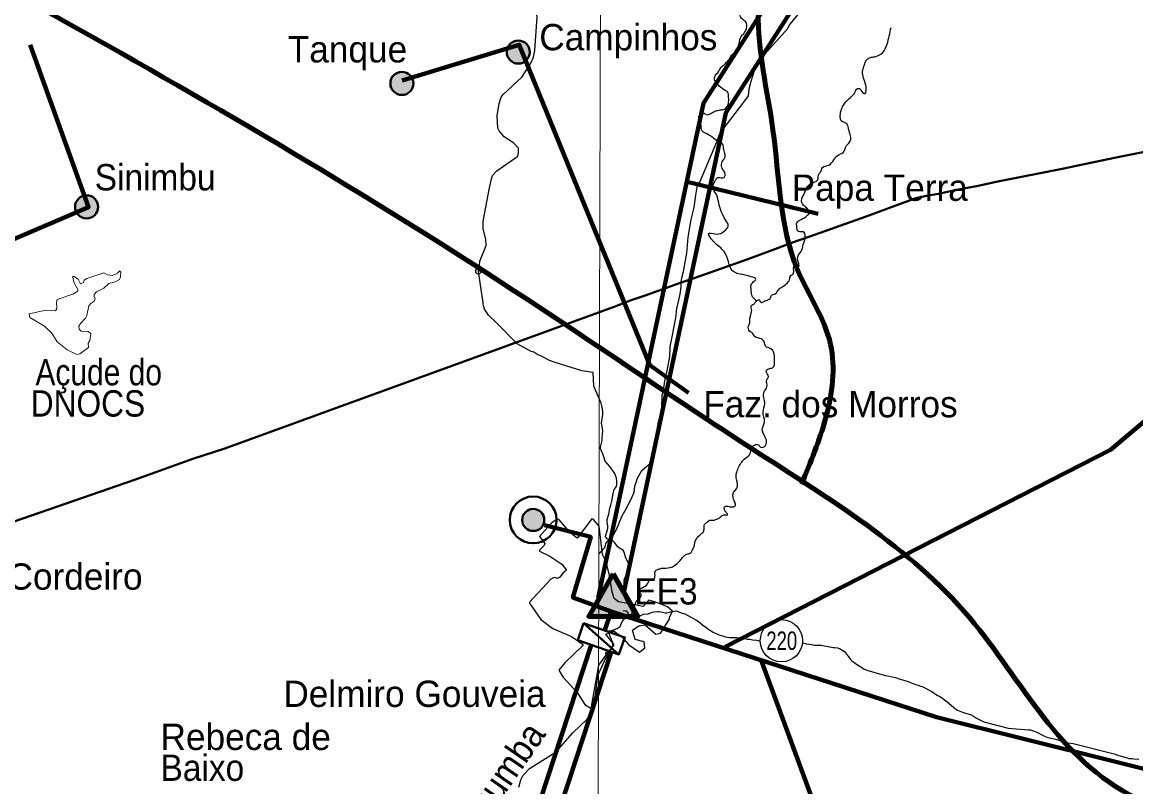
# Model space of a CAD drawing. Extents: x 553962 to 842807, y 8883888 to 9032388.
# Drawn here: x 598851 to 619995, y 8958889 to 8973416 of the extents above; entities that cross this region are included whole.
import ezdxf
from ezdxf.enums import TextEntityAlignment as Align

# ---------------------------------------------------------------- set-up
doc = ezdxf.new("R2010")
doc.units = 0
doc.header["$LTSCALE"] = 200
doc.header["$PDMODE"] = 32
doc.header["$PDSIZE"] = 100
for name, color, linetype, lineweight in [('1', 7, 'Continuous', 13), ('12', 7, 'Continuous', 25), ('21', 7, 'Continuous', 25), ('22', 7, 'Continuous', 13), ('24', 7, 'Continuous', 25), ('28', 7, 'Continuous', 40), ('41', 7, 'Continuous', 40), ('48', 7, 'Continuous', 25), ('9', 7, 'Continuous', 90)]:
    doc.layers.add(name, color=color, linetype=linetype, lineweight=lineweight)
doc.layers.add('49', color=7, linetype='Continuous')
doc.layers.add('50', color=7, linetype='Continuous')

msp = doc.modelspace()

# ---------------------------------------------------------------- hatches: boundary and pattern name
at = {"layer": '28'}
for points in [[(608763.6, 8963959.3, 1), (608342.8, 8963959.3, 1)], [(610074, 8962934.3), (610540.1, 8962126.9), (609607.9, 8962126.9)]]:
    msp.add_hatch(color=256, dxfattribs=at).paths.add_polyline_path(points)
at = {"layer": '41'}
for points in [[(608487.7, 8972849.2, 1), (608050.1, 8972849.2, 1)], [(606278, 8972253.9, 1), (605840.4, 8972253.9, 1)], [(600290.8, 8969907.7, 1), (599853.1, 8969907.7, 1)]]:
    msp.add_hatch(color=256, dxfattribs=at).paths.add_polyline_path(points)

# ---------------------------------------------------------------- linework, layer by layer
at = {"layer": '1'}
msp.add_lwpolyline([(609971.9, 9023551.8), (609764.7, 8949706.7), (609734.2, 8939404.4)], dxfattribs=at)
at = {"layer": '12'}
for points in [[(612832.5, 8972676.8), (613380.5, 8973289.6), (613425.9, 8973370.8), (613657.1, 8973648.4)], [(612040.3, 8971143.9), (612075.9, 8971248.3), (612161.5, 8971384.7), (612387.3, 8971680.5), (612554.1, 8971895.1), (612640.6, 8972015.5), (612654.9, 8972153.7), (612690.4, 8972298), (612756.6, 8972498.4), (612812.5, 8972654.7), (612832.5, 8972676.8)], [(611360.5, 8968467.9), (611360.9, 8968494.9), (611366.6, 8968506), (611377.4, 8968558.1), (611408, 8968681.3), (611469.3, 8969025.9), (611498.7, 8969332.5), (611555.6, 8969669.1), (611608.8, 8969893.5), (611644.5, 8970132.9), (611675.2, 8970318.3), (611717, 8970376.4), (612040.3, 8971143.9)], [(610973, 8965953.3), (610994.3, 8966098.6), (611002.5, 8966316), (611033.2, 8966472.2), (611059.2, 8966633.6), (611105, 8966822.9), (611145.7, 8967062.3), (611155.3, 8967247.7), (611194.3, 8967437), (611259.2, 8967798.7), (611279.7, 8967975), (611318.7, 8968135.3), (611346, 8968249.5), (611361.8, 8968386.8), (611360.5, 8968467.9)], [(609806.8, 8963316.2), (609840.1, 8963350.5), (609910.5, 8963433.7), (609927.6, 8963470.8), (609929.6, 8963512.9), (609970.7, 8963564), (610080.1, 8963678.4), (610134.1, 8963777.6), (610234.6, 8964027.2), (610293.4, 8964122.4), (610411.7, 8964351), (610469.1, 8964484.3), (610483.5, 8964599.5), (610535.5, 8964754.8), (610616.8, 8964899.1), (610667.4, 8964945.3), (610786.4, 8965043.6), (610825.3, 8965173.9), (610880.8, 8965525.5), (610933.4, 8965820.1), (610973, 8965953.3)], [(610264.1, 8962237.4), (610311.1, 8962234.5), (610316, 8962231.5), (610349.4, 8962192.5), (610374.6, 8962139.5), (610404.7, 8962083.4), (610408.2, 8962079.4), (610506.1, 8962105.6), (610649.1, 8962166.9), (610736.5, 8962174.1), (610812.1, 8962204.2), (610848.7, 8962215.3), (610911.8, 8962219.4), (610943.7, 8962217.5), (611006.1, 8962203.6), (611065.8, 8962194.6), (611093.8, 8962196.7), (611122.5, 8962202.7), (611157.7, 8962212.8), (611189.8, 8962219.9), (611269.6, 8962231), (611402.6, 8962182.1), (611435.5, 8962173.2), (611490.1, 8962144.2), (611638.5, 8962063.3), (611691.1, 8962029.4), (611771.1, 8961966.4), (611829.3, 8961918.4), (611889.1, 8961876.4), (611971.1, 8961828.5), (611997.8, 8961813.5), (612050.6, 8961788.6), (612077, 8961777.6), (612125.6, 8961761.6), (612153.7, 8961756.7), (612204.9, 8961738.7), (612281.6, 8961727.8), (612380.1, 8961723), (612410.5, 8961723), (612515.1, 8961715.2), (612566.3, 8961705.2), (612591.9, 8961698.3), (612616.6, 8961694.3), (612643, 8961692.3), (612669.5, 8961691.4), (612719.8, 8961683.5), (612795.6, 8961675.6), (612823.8, 8961668.6), (612864.6, 8961663.8)], [(613672.1, 8961625.4), (613738.4, 8961606.9), (613840.6, 8961591.1), (613866.3, 8961585.1), (613888.9, 8961581.1), (613942.1, 8961579.2), (613971.7, 8961581.3), (614023.1, 8961578.3), (614049.5, 8961572.4), (614124.5, 8961561.5), (614153.6, 8961554.5), (614252.3, 8961537.6), (614280.5, 8961536.7), (614332.5, 8961530.8), (614382, 8961510.8), (614463.3, 8961460.9), (614523.8, 8961379.8), (614532.2, 8961372.8), (614580.2, 8961308.8), (614605.9, 8961280.8), (614728.6, 8961192.9), (614806.5, 8961149.9), (614838.9, 8961123.9), (614908, 8961095), (615024.6, 8961065.1), (615056.6, 8961054.2), (615245.1, 8961000.4), (615313.2, 8960990.5), (615372, 8960976.5), (615403.6, 8960970.6), (615432.5, 8960962.6), (615523, 8960932.7), (615612.4, 8960910.8), (615673, 8960889.9), (615762.6, 8960853), (615820.4, 8960833), (615879.2, 8960814.1), (615910, 8960801.1), (615940.9, 8960791.2), (616125.3, 8960698.3), (616228.1, 8960625.3), (616267.4, 8960608.4), (616387.9, 8960522.4), (616444.1, 8960477.5), (616541.1, 8960393.5), (616575, 8960367.5), (616612, 8960346.5), (616675.8, 8960318.6), (616704.8, 8960308.6), (616763.6, 8960286.7), (616854.8, 8960258.8), (616911.9, 8960228.8), (616972.5, 8960193.8), (617033, 8960160.9), (617107.9, 8960123.1)], [(617107.9, 8960123.1), (617571.3, 8960000.1), (617961.2, 8959971.1), (617997, 8959967.1), (618026, 8959959.2), (618054, 8959949.2), (618114.7, 8959924.2), (618235.7, 8959862.3), (618293.7, 8959838.4), (618327.5, 8959827.4), (618413, 8959804.5), (618473.5, 8959791.6), (618533.2, 8959772.7), (618617.9, 8959748.8), (618652.5, 8959740.8), (618682.4, 8959731.8), (618711.4, 8959723.9), (618803.6, 8959709), (619586.3, 8959511.3)], [(619586.3, 8959511.3), (619636.3, 8959496), (619674.1, 8959485), (619831.3, 8959436.2)], [(619831.3, 8959436.2), (619865.1, 8959428.2), (619897.1, 8959423.3), (619929, 8959423.3), (619960.1, 8959421.4), (620056, 8959410.5)]]:
    msp.add_lwpolyline(points, dxfattribs=at)
at = {"layer": '12', "lineweight": 40}
for points in [[(621405.3, 8971207.1), (621164.3, 8971156.6), (620679.5, 8971055.7), (620194.7, 8970957.7), (619622.5, 8970843.7), (619047.4, 8970728.6), (618626.9, 8970634.8), (618210.5, 8970553), (617794.1, 8970471.2), (617379.1, 8970389.4), (616970.9, 8970302.6), (616723.1, 8970254.2)], [(616723.1, 8970254.2), (616475.2, 8970206.7), (616247.5, 8970158.2), (616024, 8970116.8), (615816.8, 8970075.4), (615681.8, 8970025.2), (615145.1, 8969827), (614804, 8969702.3), (614465.5, 8969579.5), (614127, 8969456.8), (613790, 8969340.1), (613461.1, 8969222.4), (613140.4, 8969103.7), (612819.7, 8968986), (612449.8, 8968852.2), (612021.1, 8968699.3), (611592.4, 8968549.4), (611360.5, 8968467.9)], [(611360.5, 8968467.9), (611013.3, 8968346.2), (610681, 8968223.4), (610434.1, 8968141.9), (610250.3, 8968070.5), (610141.5, 8968028.3), (609861, 8967928.7)], [(593118.3, 8961975.5), (594700.8, 8962547.5), (600985.5, 8964722.4), (602091.6, 8965119.9), (602697.1, 8965318.9), (609861, 8967928.7)]]:
    msp.add_lwpolyline(points, dxfattribs=at)
at = {"layer": '21'}
for points in [[(609804.3, 8963841.6), (609692.8, 8963976.2), (609666.6, 8963982.7), (609387.8, 8963613.5), (609268.7, 8963704.3), (609037.7, 8963969.7), (609005.2, 8963976.3), (608907.9, 8963902.9), (608765.2, 8963749.4), (608768.4, 8963752.9)], [(608768.4, 8963752.9), (608671.8, 8963644.5), (608771.6, 8963513.5), (608763, 8963472.8), (608674.7, 8963384.3), (608674.6, 8963362.6), (608871.1, 8963271.6), (609098.6, 8963116.9), (609185.2, 8963006.2), (609122.6, 8962955.4), (609059.5, 8962870.7), (609020.3, 8962848.1), (608953.3, 8962867.3), (608890.2, 8962830.9), (608482.3, 8962396.3), (608482.2, 8962374.6), (608698.7, 8962069.7), (608927.4, 8961894.7), (609281.9, 8961745.5), (609500, 8961592.1), (609485, 8961557.5), (609154.4, 8961246.1), (609040.8, 8961101.4), (609119, 8960979.5), (609387.8, 8960677.5), (609534.3, 8960449.1), (609653.8, 8960372.8), (609800.8, 8961196.1)], [(609800.8, 8961196.1), (609951.3, 8961405.5), (610091.2, 8961585.5), (609931.3, 8961785.4), (610001.3, 8961815.4), (610061.2, 8961845.4), (610091.2, 8961845.4), (610231.1, 8961745.4), (610371.1, 8961585.5), (610570.9, 8961445.5), (610670.8, 8961525.5), (610660.9, 8961645.5), (610491, 8961685.5), (610461, 8961775.4), (610441, 8961865.4), (610560.9, 8961945.4), (610680.8, 8961965.4), (610880.7, 8961785.4), (610970.7, 8961805.4), (611140.5, 8962075.3), (611140.5, 8962105.3), (611200.5, 8962225.3), (611100.6, 8962305.2), (610880.7, 8962395.2), (610750.8, 8962435.2), (610640.9, 8962315.2), (610391, 8962365.2), (610171.2, 8962405.2), (610091.2, 8962465.2), (610051.2, 8962595.2), (610001.3, 8962905.1), (609941.3, 8963165), (609871.4, 8963304.9), (609804.3, 8963841.6)]]:
    msp.add_lwpolyline(points, dxfattribs=at)
at = {"layer": '22'}
for points in [[(599809.1, 8968571.9), (599807.2, 8968579.6), (599825.8, 8968589.3), (599913, 8968531.8), (599957.7, 8968446.1), (600016.8, 8968470.3), (600024, 8968513.4), (600074.7, 8968549.4), (600397.5, 8968653.6), (600470.2, 8968613.3), (600565, 8968605), (600658.8, 8968647.2), (600702.7, 8968690.5), (600704.6, 8968688.3)], [(600704.6, 8968688.3), (600721.8, 8968668.3), (600716.4, 8968577.4), (600697.2, 8968526.2), (600615.2, 8968484), (600495.5, 8968451.8), (600399.8, 8968360.6), (600257.6, 8968290.3), (600215.3, 8968243.9), (600215.2, 8968203.3), (600238.2, 8968158.5), (600215, 8968118.4), (600157.8, 8968080.1), (600117.6, 8968027.2), (600078.7, 8967845.6), (600049.3, 8967791.2), (599953.8, 8967693.5), (599926.3, 8967638.5), (599930.5, 8967583.1), (599969.1, 8967544.5), (600104.8, 8967540.5), (600151.1, 8967502.5), (600134.3, 8967366.4), (600104.7, 8967317.5), (600109.2, 8967237.7)], [(598979.7, 8967874.9), (598979.6, 8967875.5), (599301.7, 8967946.2), (599480.2, 8967933.8), (599509.8, 8967969.9), (599501.3, 8968101.1), (599516.3, 8968150.1), (599811.5, 8968247.9), (599904.8, 8968303.2), (599909, 8968337.3), (599832.8, 8968479.3), (599809.1, 8968571.9)], [(599516.6, 8967344.8), (599411.9, 8967506.8), (599276.3, 8967640.2), (598993.8, 8967806), (598979.7, 8967874.9)], [(600109.2, 8967237.7), (599943.1, 8967117.9), (599886.4, 8967105.1), (599701.2, 8967194.2), (599516.6, 8967344.8)]]:
    msp.add_lwpolyline(points, dxfattribs=at)
at = {"layer": '24'}
msp.add_line((607511.6, 8968680.9), (607530.5, 8968802.4), dxfattribs=at)
for points in [[(607981.4, 8972045.9), (608340.3, 8972373.2), (608504, 8972626.3), (608557, 8972753.5), (608584.6, 8972880.9), (608629.2, 8973517.9), (608582.5, 8973773.1), (608506, 8973879.6), (608465.7, 8974028), (608448.7, 8974219.2), (608463.5, 8974525.1), (608412.1, 8974909.8)], [(608277, 8970937.8), (608271.1, 8971022.2), (608185.2, 8971119.9), (608000.5, 8971241), (607905, 8971351.2), (607881.9, 8971405.8), (607866.6, 8971636.1), (607904.8, 8971873.7), (607947.8, 8971995.4), (607981.4, 8972045.9)], [(607724.4, 8970268.8), (607758.4, 8970442.5), (607781.8, 8970504.1), (607860.2, 8970591), (608262.7, 8970873.9), (608277.1, 8970936.2), (608277, 8970937.8)], [(607530.5, 8968802.4), (607541.7, 8968874.6), (607660.5, 8969172.2), (607652.1, 8969290.7), (607601.1, 8969498.9), (607601.1, 8969639.1), (607724.4, 8970268.8)], [(607703.2, 8967850.5), (607627.7, 8967964.3), (607614.9, 8968008), (607605.5, 8968061.2), (607601.1, 8968086.8), (607511.6, 8968680.9)], [(608515.8, 8967162.6), (608251.1, 8967306.9), (607860.2, 8967694.8), (607703.2, 8967850.5)], [(609474.2, 8966790.4), (608973.4, 8966950.1), (608864.6, 8966990.5), (608731.8, 8967057), (608620.3, 8967109.1), (608563.4, 8967149.5), (608515.8, 8967162.6)], [(609841.5, 8966176.9), (609704.1, 8966503.7), (609693, 8966762.7), (609474.2, 8966790.4)], [(610371.4, 8962976.2), (610379.8, 8963013.8), (610382.1, 8963047.9), (610367.5, 8963120), (610314.8, 8963239.1), (610282.3, 8963338.2), (610265.4, 8963370.2), (610232.8, 8963402.2), (610193.3, 8963421.2), (610157.8, 8963448.2), (610095.6, 8963532.2), (610066.7, 8963561.2), (610036.6, 8963580.2), (610003.6, 8963581.1), (609956.2, 8963599.1), (609936, 8963623.1), (609928.6, 8963640.1), (609929.5, 8963669.1), (609954.4, 8963735.3), (609968.3, 8963800.4), (609967.7, 8963842.5), (609955.3, 8963923.6), (609957.6, 8963969.7), (609987.3, 8964065.8), (610009.7, 8964184.1), (610029.9, 8964242.2), (610049.4, 8964318.3), (610070.6, 8964459.6), (610090.6, 8964534.7), (610118.8, 8964569.8), (610136.5, 8964599.9), (610143.2, 8964627), (610143.3, 8964686.1), (610132.5, 8964751.1), (610117.5, 8964805.2), (610101.9, 8964839.2), (610009.9, 8964971.3), (609920.5, 8965076.3), (609887.1, 8965177.4), (609832.3, 8965315.6), (609830, 8965343.6), (609859.8, 8965469.8), (609861.1, 8965523.9), (609875.2, 8965654.1), (609872.3, 8965696.2), (609853, 8965796.3), (609874, 8965961.6), (609874.8, 8965999.7), (609869.2, 8966072.8), (609858.8, 8966126.9), (609841.5, 8966176.9)], [(609982.1, 8961422.7), (610037.1, 8961507.9), (610064.5, 8961578.1), (610064.2, 8961638.2), (610040.6, 8961677.2), (610038.1, 8961690.2), (610013.3, 8961743.3), (609992.6, 8961823.3), (609993.5, 8961853.4), (609997.6, 8961856.4), (610025.7, 8961851.5), (610048.1, 8961855.5), (610148.5, 8961896.7), (610207.6, 8961933.9), (610245.1, 8962026.1), (610277.6, 8962073.2), (610312.8, 8962103.3), (610398.6, 8962138.5), (610419.5, 8962164.6), (610435.7, 8962195.6), (610437.2, 8962206.7), (610284.5, 8962485.8), (610279.8, 8962547.9), (610295.5, 8962684.2), (610281.3, 8962752.3), (610279.8, 8962791.3), (610289, 8962838.4), (610320, 8962910.6), (610338.8, 8962938.6), (610371.4, 8962976.2)], [(608279.8, 8958879.3), (608317, 8959022.3), (608365.8, 8959111.5), (608484.8, 8959236.8), (608990.2, 8959553.2), (609306.9, 8959910.2), (609576.6, 8960175.8), (609697.7, 8960350), (609780.5, 8960992), (609809.8, 8961070.9), (609834, 8961110), (609904.8, 8961278.4), (609982.1, 8961422.7)]]:
    msp.add_lwpolyline(points, dxfattribs=at)
for points in [[(612667.9, 8967747.4), (612667.9, 8967790.6), (612680.2, 8967833.7), (612689.4, 8967892.3), (612701.8, 8967938.6), (612692.5, 8967987.9), (612692.5, 8968024.9), (612726.4, 8968049.6), (612775.7, 8968098.9), (612785, 8968114.3), (612741.8, 8968172.9), (612704.8, 8968231.5), (612692.5, 8968339.4), (612692.5, 8968425.8), (612738.8, 8968487.5), (612781.9, 8968533.7), (612694.2, 8968580), (612482.9, 8968630.8), (612373, 8968664.6), (612212.4, 8969002.9), (612043.3, 8969189), (611899.7, 8969349.7), (611882.8, 8969392), (612026.5, 8969392), (612187.1, 8969451.2), (612254.7, 8969544.2), (612204, 8969662.7), (612077.2, 8969984.1), (612026.5, 8970153.2), (611967.3, 8970271.6), (612018, 8970415.4), (612059.6, 8970464.8), (612178.6, 8970464.8), (612198.5, 8970524.3), (612143.9, 8970638.6), (612134, 8970737.9), (612183.6, 8970832.2), (612198.5, 8970901.7), (612173.7, 8970996.1), (612153.8, 8971095.4), (612034.7, 8971169.8), (611950.4, 8971234.4), (611811.4, 8971313.8), (611756.8, 8971358.5), (611742, 8971462.8), (611712.2, 8971557.2), (611702.3, 8971636.6), (611756.8, 8971686.2), (611801.5, 8971686.2), (611829.2, 8971666.8), (611881.3, 8971661.6), (611964.6, 8971705.9), (612040.2, 8971737.1), (612128.7, 8971752.8), (612212, 8971778.8), (612238.1, 8971812.7), (612258.9, 8971872.6), (612264.1, 8971989.9), (612258.9, 8972052.5), (612245.9, 8972091.6), (612199, 8972120.2), (612087, 8972203.6), (612029.7, 8972268.8), (611993.3, 8972341.7), (612000.3, 8972381.2), (612077.3, 8972484.1), (612113.3, 8972556.1), (612180.2, 8972607.5), (612231.6, 8972664.1), (612288.1, 8972725.8), (612318.9, 8972792.7), (612396, 8972854.4), (612426.9, 8972905.8), (612468, 8973024.1), (612498.8, 8973137.3), (612550.2, 8973199), (612601.6, 8973286.4), (612606.8, 8973368.7), (612596.5, 8973409.9), (612524.5, 8973471.6), (612478.3, 8973553.9), (612462.8, 8973646.5), (612370.3, 8973888.2), (612396, 8973991.1), (612432, 8974057.9), (612406.3, 8974140.2), (612416.6, 8974160.8), (612473.1, 8974181.4), (612555.4, 8974299.7), (612622.2, 8974397.4), (612653, 8974423.1)], [(612786.7, 8968107.3), (612801.6, 8968128.4), (612825.4, 8968137.6), (612841.8, 8968141.2), (612849.1, 8968135.7), (612863.8, 8968104.6), (612885.7, 8968091.8), (612907.7, 8968095.5), (612936.9, 8968110.1), (612958.9, 8968126.6), (613002.8, 8968135.7), (613019.2, 8968144.9), (613052.1, 8968168.7), (613075.9, 8968223.6), (613149.1, 8968256.5), (613222.2, 8968346.2), (613291.7, 8968393.7), (613379.5, 8968463.3), (613410.6, 8968499.9), (613419.7, 8968521.8), (613428.9, 8968573.1), (613434.3, 8968587.7), (613492.9, 8968642.6), (613500.2, 8968675.6), (613500.2, 8968774.4), (613520.8, 8968819.7), (613563.5, 8968810.2), (613601.5, 8968781.7), (613573, 8968914.7), (613639.4, 8969062), (613682.2, 8969190.2), (613720.1, 8969337.5), (613710.7, 8969399.2), (613677.4, 8969432.5), (613601.5, 8969437.2), (613577.7, 8969451.5), (613558.7, 8969522.8), (613558.7, 8969603.5), (613644.2, 8969670), (613758.1, 8969741.3), (613791.3, 8969793.5), (613772.4, 8969850.5), (613667.9, 8969964.5), (613648.9, 8970026.3), (613691.7, 8970145), (613767.6, 8970301.8), (613881.6, 8970377.8), (613929, 8970392), (613962.2, 8970444.3), (613976.5, 8970529.8), (614009.7, 8970567.8), (614047.7, 8970658), (614166.4, 8970700.8), (614261.3, 8970800.5), (614342, 8970890.8), (614437, 8970938.3), (614503.4, 8971071.3), (614560.4, 8971137.8), (614584.1, 8971209.1), (614565.1, 8971304.1), (614531.9, 8971432.3), (614503.4, 8971489.3), (614403.7, 8971541.6), (614384.7, 8971608.1), (614399, 8971741.1), (614508.2, 8971921.6), (614660.1, 8972083.1), (614712.3, 8972154.3), (614750.3, 8972154.3), (614793, 8972097.3), (614854.7, 8972064.1), (614873.7, 8972111.6), (614816.7, 8972387.1), (614812, 8972505.8), (614840.4, 8972594.7), (614887.9, 8972703.9), (614973.4, 8972751.4), (615039.8, 8972760.9), (615187, 8972836.9), (615272.4, 8972998.4), (615315.2, 8973159.9), (615348.4, 8973316.7)], [(610437.2, 8962206.7), (610489.2, 8962352.5), (610507, 8962405.6), (610591.1, 8962494.2), (610608.8, 8962534.1), (610569, 8962587.3), (610569, 8962636), (610622.1, 8962671.5), (610723.9, 8962746.8), (610781.5, 8962826.6), (610843.5, 8962831), (610865.6, 8962932.9), (610878.9, 8962999.4), (610927.6, 8963021.5), (610989.6, 8963039.3), (611153.5, 8963052.6), (611237.6, 8963092.4), (611326.2, 8963170.3), (611391.1, 8963243.8), (611437.2, 8963291.6), (611507.3, 8963317.3), (611551.7, 8963341.2), (611579, 8963390.8), (611611.5, 8963460.9), (611625.2, 8963534.4), (611655.9, 8963601), (611737.9, 8963688.2), (611785.7, 8963732.7), (611797.7, 8963804.5), (611808, 8963871.1), (611830.2, 8963895.1), (611896.8, 8963948.1), (611919, 8963954.9), (611970.2, 8963951.5), (612038.6, 8963975.4), (612098.4, 8964004.5), (612127.4, 8964033.5), (612190.6, 8964055.8), (612224.8, 8964050.6), (612238.5, 8964052.3), (612240.2, 8964069.4), (612206, 8964115.6), (612185.5, 8964161.7), (612177, 8964187.4), (612183.8, 8964207.9), (612226.5, 8964221.6), (612276, 8964211.3), (612310.2, 8964206.2), (612354.6, 8964207.9), (612385.4, 8964225), (612393.9, 8964254), (612385.4, 8964289.9), (612343.5, 8964423.3), (612364, 8964491.7), (612418.7, 8964560.1), (612432.3, 8964642.1), (612411.8, 8964731), (612405, 8964792.5), (612418.7, 8964867.8), (612514.3, 8965059.2), (612562.2, 8965113.9), (612657.8, 8965196), (612753.5, 8965380.6), (612828.7, 8965387.4), (612876.5, 8965339.6), (612965.4, 8965373.7), (612931.2, 8965585.7), (612903.9, 8965667.8), (612944.9, 8965818.2), (612917.5, 8966009.7), (612951.7, 8966173.8), (612931.2, 8966378.9), (612992.7, 8966488.3), (612992.7, 8966625.1), (613020, 8966679.8), (612979, 8966789.2), (613026.9, 8966830.2), (613095.2, 8966850.7), (613136.2, 8967014.8), (613067.9, 8967213.1), (612965.4, 8967261), (612938, 8967343), (612883.4, 8967397.7), (612787.7, 8967425.1), (612753.5, 8967452.4), (612705.7, 8967520.8), (612658.6, 8967543.9), (612640.1, 8967590.1), (612640.1, 8967642.6), (612667.9, 8967707.3), (612667.9, 8967747.4)]]:
    msp.add_spline(points, degree=3, dxfattribs=at)
for p in [(607511.6, 8968680.9), (609982.1, 8961422.7)]:
    msp.add_point(p, dxfattribs=at)
at = {"layer": '28', "lineweight": 80}
for p, q in [((611453.6, 8970388.8), (613965.9, 8969778.7)), ((610031.8, 8962217.2), (609916, 8961864)), ((612881.2, 8961293.3), (614572.2, 8956699.9))]:
    msp.add_line(p, q, dxfattribs=at)
for points in [[(609785.7, 8962480.2), (611783.9, 8971876.8), (614204.9, 8975668.6)], [(610282, 8962611.2), (612213.1, 8971692.7), (614696.7, 8975582.5)], [(596480.2, 8968348.2), (600111.2, 8969905.3), (599003, 8972985.3)], [(611500.2, 8966375.3), (610770.7, 8966898.6), (608287.5, 8972987.9), (606067.3, 8972308.3)], [(612196.3, 8961548), (619517.6, 8965291.5), (621276.7, 8966775.5)], [(608766.3, 8963860), (609644.5, 8963637.7), (609306, 8962483.6), (610031.8, 8962217.2)], [(610031.8, 8962217.2), (616214.5, 8960212.5), (621246, 8958953.8), (627155.1, 8953509.2), (629934.5, 8948091.8)], [(609654.9, 8961582), (607705.3, 8955637.1), (606570.7, 8953736.9)], [(610035, 8961447.4), (608003.1, 8955251.4), (606868.5, 8953351.2)]]:
    msp.add_lwpolyline(points, dxfattribs=at)
at = {"layer": '28', "lineweight": 90}
msp.add_lwpolyline([(610074, 8962934.3), (610540.1, 8962126.9), (609607.9, 8962126.9)], close=True, dxfattribs=at)
at = {"layer": '28'}
msp.add_lwpolyline([(609510.1, 8961997.5), (610294, 8961725.4), (610181.9, 8961402.4), (609398, 8961674.5)], close=True, dxfattribs=at)
for points in [[(609510.1, 8961997.5), (609398, 8961674.5), (610181.9, 8961402.4)], [(609510.1, 8961997.5), (610181.9, 8961402.4), (609510.1, 8961997.5)]]:
    msp.add_lwpolyline(points, dxfattribs=at)
for radius in [444.4, 210.4]:
    msp.add_circle((608553.2, 8963959.3), radius, dxfattribs=at)
at = {"layer": '41'}
for centre in [(608268.9, 8972849.2), (606059.2, 8972253.9), (600072, 8969907.7)]:
    msp.add_circle(centre, 218.8, dxfattribs=at)
at = {"layer": '48'}
msp.add_circle((613266.4, 8961662.9), 401.3, dxfattribs=at)
at = {"layer": '9'}
for points in [[(607019.9, 8987628.8), (608117.9, 8987072.5), (609319, 8986220.3), (609831, 8985717.6), (610444.6, 8985240.9), (611083, 8984865.7), (611314.6, 8984437), (611367.4, 8984108.2), (611371.5, 8983424.7), (611351.3, 8982538.5), (611228.8, 8981727.5), (611158.3, 8980739.6), (611137.7, 8979929.4), (611547.1, 8979552.5), (611828.5, 8979301.3), (612340.6, 8978773.3), (612648.8, 8978294.5), (612832.8, 8977308.5), (612940.5, 8976321.9), (612949.5, 8974803), (612829.3, 8973612.2), (613105.4, 8971372.7), (613572.8, 8968712.3), (614200.8, 8967292.3), (614110, 8965907), (613645.9, 8964639.4)], [(592698.5, 8977198.4), (599903.5, 8973292.7), (608459.2, 8968138.2), (612674.8, 8965332.6), (616842, 8962096.4), (620005, 8958671.2), (621134, 8957974.7), (621473.4, 8956805.3), (621586.2, 8956597.5)]]:
    msp.add_spline(points, degree=3, dxfattribs=at)

# ---------------------------------------------------------------- texts
at = {"layer": '28', "width": 0.95}
msp.add_text('EE3', height=500, dxfattribs=at).set_placement((610475.1, 8962351.9))
at = {"layer": '41'}
for s, p in [('Campinhos', (608668.4, 8972882.8)), ('Tanque', (603892.7, 8972652.3)), ('Papa Terra', (613461.5, 8970022.2)), ('Faz. dos Morros', (611783, 8965909.2)), ('Faz. Cordeiro', (597085.2, 8962633.5)), ('Delmiro Gouveia', (603808.9, 8960405.2)), ('Rebeca de', (601476.7, 8959587))]:
    msp.add_text(s, height=500, dxfattribs=at).set_placement(p)
at = {"layer": '41', "width": 0.95}
for s, p in [('Sinimbu', (600227.1, 8970220.9)), ('Baixo', (601476.7, 8959000.1))]:
    msp.add_text(s, height=500, dxfattribs=at).set_placement(p)
at = {"layer": '48', "width": 0.75}
msp.add_text('220', height=350, dxfattribs=at).set_placement((613273, 8961489.6), align=Align.CENTER)
at = {"layer": '49', "width": 0.95}
msp.add_text('Rio Cazumba', height=500, rotation=55.429, dxfattribs=at).set_placement((607716.8, 8958303), align=Align.CENTER)
at = {"layer": '50'}
for s, width, p in [('Açude do', 0.85, (600302.7, 8966516.8)), ('DNOCS', 0.9, (600098, 8965922.9))]:
    msp.add_text(s, height=500, dxfattribs=dict(at, width=width)).set_placement(p, align=Align.CENTER)

doc.saveas('drawing.dxf')
